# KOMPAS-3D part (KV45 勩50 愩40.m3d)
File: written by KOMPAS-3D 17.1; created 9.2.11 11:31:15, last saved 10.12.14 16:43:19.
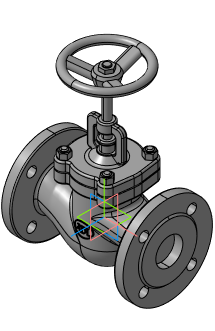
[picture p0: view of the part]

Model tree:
1. Плоскость XY
2. Плоскость ZX
3. Плоскость ZY
4. Ось X
5. Ось Y
6. Ось Z
7. Начало координат
8. Операция без истории:2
